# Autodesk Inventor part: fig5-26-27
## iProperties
Created: 2004-05
Part Number: fig5-26-27
Document SubType Name: Modeling
Designer: CADCIM Technologies
Manufacturer: Standard
Standards Organization: Custom
Author: CADCIM Technologies
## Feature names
1. Extrusion1
2. Fillet1
3. Extrusion2
4. Hole1
5. Fillet2
